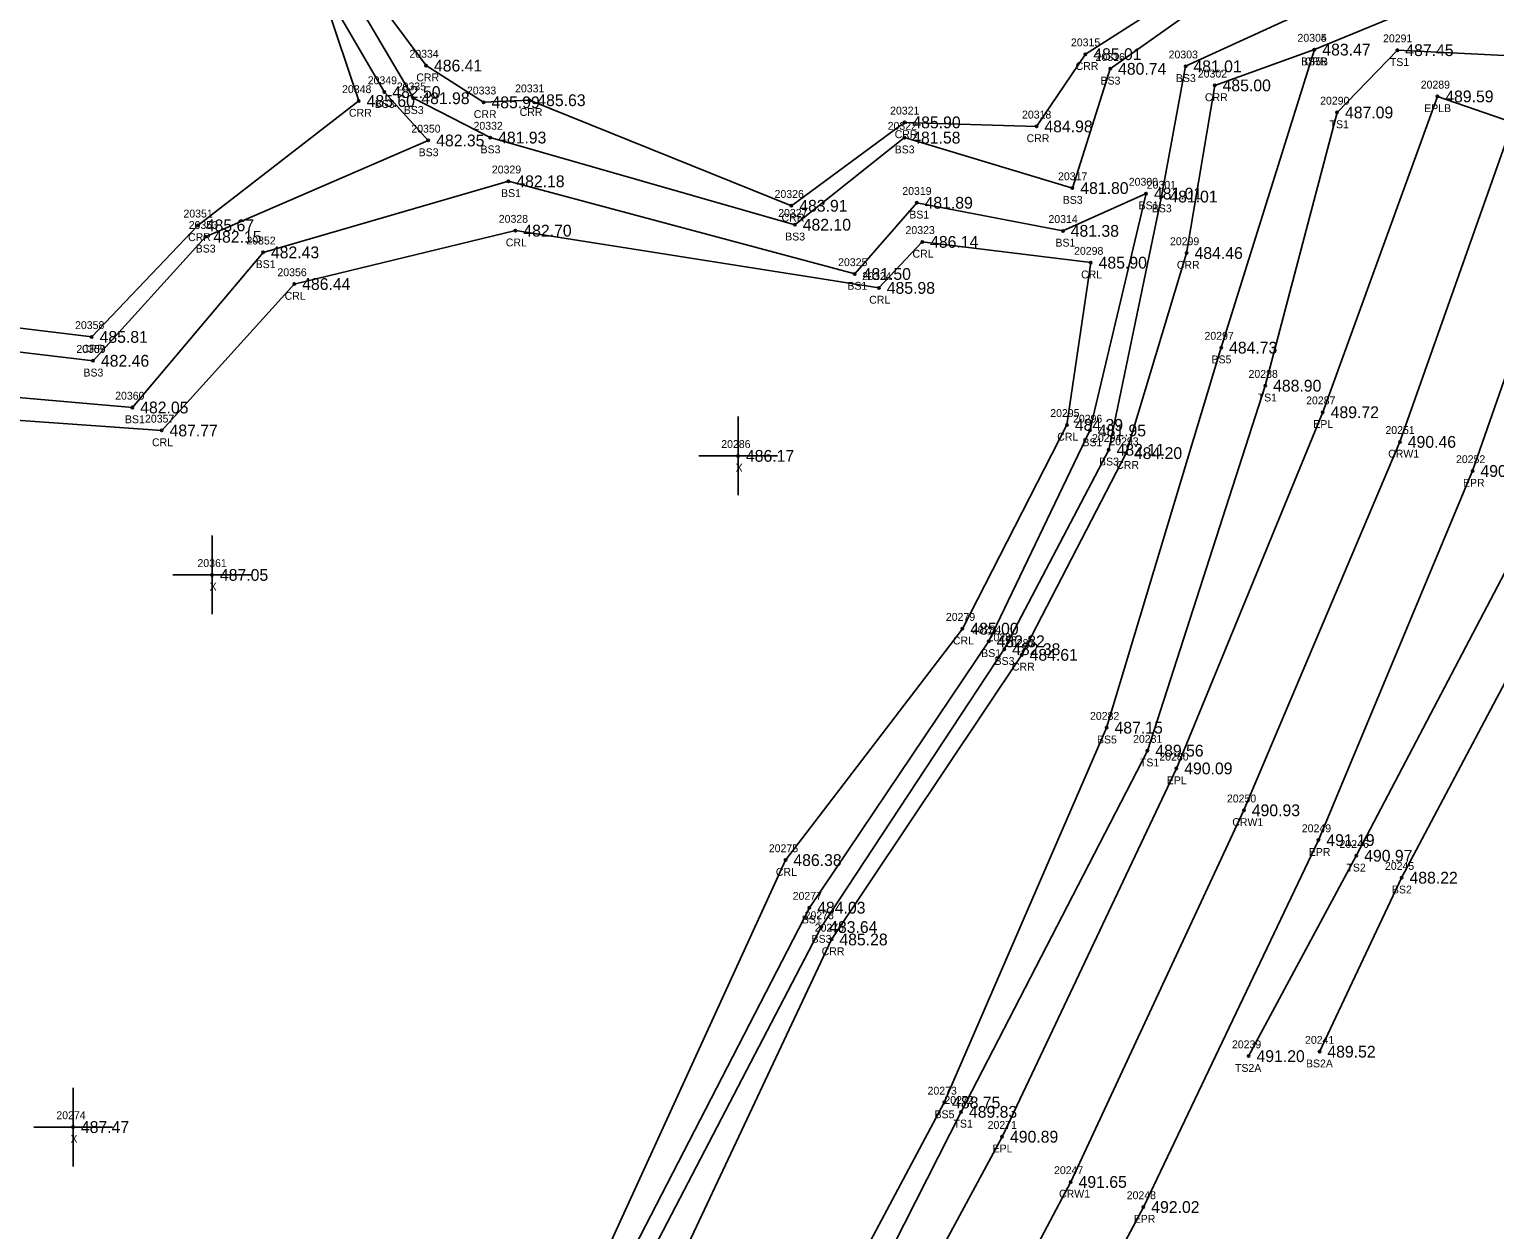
# Model space of a CAD drawing. Extents: x 1649406 to 1650436, y 896752 to 898178.
# Drawn here: x 1649688.5 to 1649874.8, y 897267.9 to 897420.5 of the extents above; entities that cross this region are included whole.
import ezdxf

# ---------------------------------------------------------------- set-up
doc = ezdxf.new("R2010")
doc.units = 0
for name, color, linetype in [('RD_DTM_BkLn1', 7, 'Continuous'), ('RD_DTM_BkLn2', 7, 'Continuous'), ('RD_DTM_BkLn_txCode', 7, 'Continuous'), ('RD_EX_H2O', 7, 'Continuous'), ('RD_EX_H2O_txCode', 7, 'Continuous'), ('RD_EX_Misc', 7, 'Continuous'), ('RD_EX_Misc_txCode', 7, 'Continuous'), ('RD_EX_Road', 7, 'Continuous'), ('RD_EX_Road_txCode', 7, 'Continuous'), ('RD_EX_TX_H2O_ELEV', 7, 'Continuous'), ('RD_EX_TX_Misc_ELEV', 7, 'Continuous'), ('RD_EX_TX_Road_ELEV', 7, 'Continuous'), ('RD_HC_Survey_ELEV', 7, 'Continuous'), ('RD_HC_Survey_txCode', 7, 'Continuous'), ('RD_SMD_Locator', 7, 'Continuous')]:
    doc.layers.add(name, color=color, linetype=linetype)

msp = doc.modelspace()

# ---------------------------------------------------------------- linework, layer by layer
at = {"layer": 'RD_DTM_BkLn1'}
msp.add_lwpolyline([(1649466.79, 896799.14), (1649494.97, 896834.25), (1649557.53, 896909.97), (1649590.88, 896950.41), (1649622.36, 896988.16), (1649622.36, 896988.48), (1649654.33, 897027.92), (1649685.38, 897067.52), (1649715.96, 897107.48), (1649743.64, 897146.32), (1649771.01, 897187.23), (1649797.64, 897230.08), (1649820.89, 897273.98), (1649842.91, 897321.22), (1649862.74, 897368.05), (1649877.08, 897408.66)], dxfattribs=at)
at = {"layer": 'RD_DTM_BkLn2'}
for points in [[(1649735.32, 897452.32), (1649735.42, 897430.71), (1649726.93, 897424.04), (1649733.64, 897412.51), (1649739.22, 897406.36), (1649710.88, 897394.12), (1649696.6, 897378.36), (1649634.62, 897385.73), (1649610.45, 897366.7), (1649591.79, 897363.75), (1649561.2, 897371.75), (1649517.81, 897366.5), (1649502.21, 897346.17), (1649434.27, 897348.24)], [(1649868.3, 897435.39), (1649845.55, 897429.41), (1649825.91, 897415.47), (1649821.11, 897400.31), (1649799.74, 897406.72), (1649785.82, 897395.65), (1649747.09, 897406.73), (1649737.33, 897411.73), (1649729.69, 897424.71), (1649738.08, 897430.82), (1649737.7, 897451.57)], [(1649604.6, 897005.75), (1649602.47, 897009.39), (1649602.3, 897017.91), (1649611.46, 897066.62), (1649609.91, 897087.35), (1649647.02, 897127.55), (1649667.48, 897155.95), (1649673.52, 897172.2), (1649701.06, 897200.6), (1649725.89, 897215.14), (1649740.6, 897244.69), (1649756.42, 897243.48), (1649789.18, 897306.38), (1649812.44, 897341.7), (1649825.72, 897367.05), (1649832.43, 897399.23), (1649835.49, 897415.79), (1649852.17, 897423.43), (1649870.24, 897429.91)], [(1649709.8, 897128.5), (1649729, 897156.36), (1649754.58, 897196.69), (1649780.91, 897239.21), (1649804.81, 897284.08), (1649825.46, 897331.72), (1649840.02, 897380.03), (1649851.88, 897417.91)], [(1649711.48, 897127.33), (1649731.83, 897154.08), (1649758, 897194.49), (1649783.81, 897237.31), (1649806.95, 897282.89), (1649830.65, 897328.8), (1649845.62, 897375.19), (1649854.76, 897409.92), (1649862.43, 897417.84), (1649895.58, 897416.19)], [(1649852.52, 897290.54), (1649862.96, 897312.65), (1649887.44, 897358.87), (1649901.31, 897404.88), (1649900.89, 897412.99), (1649895.58, 897416.19)], [(1649843.51, 897289.97), (1649857.2, 897315.44), (1649880.99, 897360.81), (1649894.26, 897406.78), (1649892.22, 897410.41)], [(1649755.02, 897245.48), (1649787.66, 897308.84), (1649810.46, 897342.7), (1649823.33, 897369.5), (1649830.47, 897399.61), (1649819.89, 897394.87), (1649801.31, 897398.44), (1649793.44, 897389.39), (1649749.41, 897401.17), (1649718.21, 897392.14), (1649701.59, 897372.42), (1649632.22, 897378.5), (1649614.16, 897360.06), (1649591.9, 897357.3), (1649588.7, 897317.57), (1649583.25, 897284.44)]]:
    msp.add_lwpolyline(points, dxfattribs=at)
at = {"layer": 'RD_EX_H2O'}
for points in [[(1649733.89, 897452.78), (1649733.23, 897431.68), (1649726.08, 897424.3), (1649730.38, 897411.38), (1649709.93, 897395.57), (1649696.43, 897381.39), (1649633.87, 897388.98), (1649608.54, 897369.49), (1649592.36, 897367.34), (1649564.26, 897376.33), (1649519.76, 897372.2), (1649499.24, 897352.4), (1649435.41, 897352.44)], [(1649868.8, 897437.77), (1649846.16, 897432.3), (1649822.76, 897417.33), (1649816.54, 897408.15), (1649799.76, 897408.66), (1649785.38, 897398.06), (1649752.08, 897411.48), (1649746.25, 897411.21), (1649738.94, 897415.88), (1649733.55, 897423.08), (1649741.13, 897430.63), (1649738.72, 897452.07)], [(1649610.78, 897003.58), (1649606.65, 897007.8), (1649603.49, 897018.01), (1649613.66, 897065.71), (1649613.8, 897087.62), (1649648.77, 897123.4), (1649673.15, 897145.36), (1649677.84, 897170.04), (1649704.36, 897195), (1649732.98, 897211.32), (1649741.05, 897244.13), (1649760.18, 897240.39), (1649790.48, 897304.8), (1649814.66, 897340.98), (1649827.92, 897366.62), (1649835.63, 897392.05), (1649839.2, 897413.36), (1649851.88, 897417.91), (1649868.27, 897424.7)], [(1649753.58, 897247.01), (1649784.63, 897314.89), (1649807.13, 897344.3), (1649820.41, 897370.21), (1649823.44, 897390.83), (1649802.01, 897393.47), (1649796.5, 897387.62), (1649750.3, 897394.9), (1649722.18, 897388.11), (1649705.32, 897369.5), (1649633.55, 897374.58), (1649615.45, 897358.48), (1649595.58, 897353.05), (1649593.32, 897314.38), (1649587.49, 897281.56)]]:
    msp.add_lwpolyline(points, dxfattribs=at)
at = {"layer": 'RD_EX_Misc'}
for p, q in [((1649778.6, 897361.27), (1649778.6, 897371.27)), ((1649773.6, 897366.27), (1649783.6, 897366.27)), ((1649711.73, 897346.14), (1649711.73, 897356.14)), ((1649706.73, 897351.14), (1649716.73, 897351.14)), ((1649694.05, 897275.96), (1649694.05, 897285.96)), ((1649689.05, 897280.96), (1649699.05, 897280.96))]:
    msp.add_line(p, q, dxfattribs=at)
at = {"layer": 'RD_EX_Road'}
for points in [[(1649459.38, 896805.71), (1649486.55, 896839.62), (1649513.65, 896873.34), (1649538.22, 896902.56), (1649549.43, 896916.62), (1649583.1, 896957.27), (1649614.8, 896995.02), (1649647.06, 897035.69), (1649677.62, 897074.51), (1649708.33, 897114.44), (1649735.5, 897151.61), (1649762.11, 897192.19), (1649788.21, 897235.29), (1649812.17, 897279.73), (1649834.32, 897326.54), (1649852.94, 897371.82), (1649867.51, 897411.96)], [(1649892.22, 897410.41), (1649886.55, 897406.09), (1649877.08, 897408.66), (1649867.51, 897411.96)], [(1649474.75, 896792.65), (1649502.78, 896827.35), (1649565.2, 896903.92), (1649598.28, 896943.71), (1649629.8, 896982.26), (1649667.92, 897029.33), (1649693.13, 897061.44), (1649723.58, 897101.84), (1649752.37, 897141.09), (1649779.72, 897182.3), (1649806.12, 897225.84), (1649830.13, 897270.79), (1649852.39, 897317.43), (1649871.98, 897364.35), (1649886.55, 897406.09)]]:
    msp.add_lwpolyline(points, dxfattribs=at)
at = {"layer": 'RD_SMD_Locator'}
for centre in [(1649822.76, 897417.33), (1649851.88, 897417.91), (1649851.88, 897417.91), (1649862.43, 897417.84), (1649738.94, 897415.88), (1649825.91, 897415.47), (1649835.49, 897415.79), (1649839.2, 897413.36), (1649730.38, 897411.38), (1649733.64, 897412.51), (1649737.33, 897411.73), (1649752.08, 897411.48), (1649867.51, 897411.96), (1649746.25, 897411.21), (1649854.76, 897409.92), (1649799.76, 897408.66), (1649816.54, 897408.15), (1649739.22, 897406.36), (1649747.09, 897406.73), (1649799.74, 897406.72), (1649749.41, 897401.17), (1649821.11, 897400.31), (1649801.31, 897398.44), (1649830.47, 897399.61), (1649832.43, 897399.23), (1649785.38, 897398.06), (1649709.93, 897395.57), (1649750.3, 897394.9), (1649785.82, 897395.65), (1649819.89, 897394.87), (1649710.88, 897394.12), (1649802.01, 897393.47), (1649718.21, 897392.14), (1649835.63, 897392.05), (1649793.44, 897389.39), (1649823.44, 897390.83), (1649722.18, 897388.11), (1649796.5, 897387.62), (1649696.43, 897381.39), (1649840.02, 897380.03), (1649696.6, 897378.36), (1649845.62, 897375.19), (1649701.59, 897372.42), (1649852.94, 897371.82), (1649705.32, 897369.5), (1649820.41, 897370.21), (1649823.33, 897369.5), (1649825.72, 897367.05), (1649862.74, 897368.05), (1649778.6, 897366.27), (1649827.92, 897366.62), (1649871.98, 897364.35), (1649711.73, 897351.14), (1649807.13, 897344.3), (1649810.46, 897342.7), (1649812.44, 897341.7), (1649814.66, 897340.98), (1649825.46, 897331.72), (1649830.65, 897328.8), (1649834.32, 897326.54), (1649842.91, 897321.22), (1649852.39, 897317.43), (1649784.63, 897314.89), (1649857.2, 897315.44), (1649862.96, 897312.65), (1649787.66, 897308.84), (1649789.18, 897306.38), (1649790.48, 897304.8), (1649852.52, 897290.54), (1649843.51, 897289.97), (1649804.81, 897284.08), (1649806.95, 897282.89), (1649694.05, 897280.96), (1649812.17, 897279.73), (1649820.89, 897273.98), (1649830.13, 897270.79)]:
    msp.add_circle(centre, 0.15, dxfattribs=at)

# ---------------------------------------------------------------- texts
at = {"layer": 'RD_DTM_BkLn_txCode'}
for s, p in [('20305', (1649849.72, 897418.91)), ('20291', (1649860.6, 897418.84)), ('20316', (1649824.05, 897416.47)), ('20303', (1649833.34, 897416.79)), ('BS5B', (1649850.18, 897415.91)), ('TS1', (1649861.47, 897415.84)), ('20349', (1649731.52, 897413.51)), ('20335', (1649735.21, 897412.73)), ('BS3', (1649824.68, 897413.47)), ('BS3', (1649834.26, 897413.79)), ('BS3', (1649732.41, 897410.51)), ('20290', (1649852.6, 897410.92)), ('BS3', (1649736.1, 897409.73)), ('20350', (1649737.06, 897407.36)), ('20332', (1649744.97, 897407.73)), ('20322', (1649797.62, 897407.72)), ('TS1', (1649853.8, 897407.92)), ('BS3', (1649737.99, 897404.36)), ('BS3', (1649745.86, 897404.73)), ('BS3', (1649798.51, 897404.72)), ('20329', (1649747.3, 897402.17)), ('20317', (1649819.28, 897401.31)), ('20319', (1649799.48, 897399.44)), ('20300', (1649828.27, 897400.61)), ('20301', (1649830.56, 897400.23)), ('BS1', (1649748.47, 897399.17)), ('BS3', (1649819.88, 897398.31)), ('BS1', (1649829.52, 897397.61)), ('20327', (1649783.7, 897396.65)), ('BS1', (1649800.37, 897396.44)), ('20314', (1649818.06, 897395.87)), ('BS3', (1649831.2, 897397.23)), ('20353', (1649708.76, 897395.12)), ('BS3', (1649709.65, 897392.12)), ('20352', (1649716.09, 897393.14)), ('BS3', (1649784.59, 897393.65)), ('BS1', (1649818.95, 897392.87)), ('BS1', (1649717.27, 897390.14)), ('20325', (1649791.32, 897390.39)), ('BS1', (1649792.5, 897387.39)), ('20297', (1649837.9, 897381.03)), ('20359', (1649694.48, 897379.36)), ('BS5', (1649838.79, 897378.03)), ('BS3', (1649695.37, 897376.36)), ('20288', (1649843.5, 897376.19)), ('20360', (1649699.41, 897373.42)), ('TS1', (1649844.66, 897373.19)), ('BS1', (1649700.65, 897370.42)), ('20296', (1649821.18, 897370.5)), ('20294', (1649823.6, 897368.05)), ('BS1', (1649822.38, 897367.5)), ('BS3', (1649824.49, 897365.05)), ('20284', (1649808.34, 897343.7)), ('20285', (1649810.32, 897342.7)), ('BS1', (1649809.51, 897340.7)), ('BS3', (1649811.21, 897339.7)), ('20282', (1649823.34, 897332.72)), ('BS5', (1649824.23, 897329.72)), ('20281', (1649828.82, 897329.8)), ('TS1', (1649829.69, 897326.8)), ('20246', (1649855.06, 897316.44)), ('20245', (1649860.84, 897313.65)), ('TS2', (1649855.95, 897313.44)), ('BS2', (1649861.73, 897310.65)), ('20277', (1649785.54, 897309.84)), ('BS1', (1649786.71, 897306.84)), ('20278', (1649787.06, 897307.38)), ('BS3', (1649787.95, 897304.38)), ('20241', (1649850.68, 897291.54)), ('20239', (1649841.39, 897290.97)), ('TS2A', (1649841.78, 897287.97)), ('BS2A', (1649850.8, 897288.54)), ('20273', (1649802.69, 897285.08)), ('20272', (1649804.83, 897283.89)), ('BS5', (1649803.58, 897282.08)), ('TS1', (1649805.99, 897280.89))]:
    msp.add_text(s, height=1, dxfattribs=at).set_placement(p)
at = {"layer": 'RD_EX_H2O_txCode'}
for s, p in [('20315', (1649820.92, 897418.33)), ('20304', (1649849.72, 897418.91)), ('20334', (1649736.82, 897416.88)), ('CRR', (1649821.51, 897415.33)), ('20302', (1649837.05, 897414.36)), ('CRR', (1649850.62, 897415.91)), ('20348', (1649728.26, 897412.38)), ('CRR', (1649737.69, 897413.88)), ('20331', (1649750.25, 897412.48)), ('20333', (1649744.13, 897412.21)), ('CRR', (1649837.95, 897411.36)), ('CRR', (1649729.13, 897409.38)), ('CRR', (1649745, 897409.21)), ('CRR', (1649750.83, 897409.48)), ('20321', (1649797.93, 897409.66)), ('20318', (1649814.7, 897409.15)), ('CRR', (1649798.51, 897406.66)), ('CRR', (1649815.28, 897406.15)), ('20326', (1649783.24, 897399.06)), ('20351', (1649708.09, 897396.57)), ('20328', (1649748.18, 897395.9)), ('CRR', (1649784.13, 897396.06)), ('20323', (1649799.89, 897394.47)), ('CRR', (1649708.68, 897393.57)), ('CRL', (1649749.07, 897392.9)), ('20299', (1649833.51, 897393.05)), ('CRL', (1649800.78, 897391.47)), ('20298', (1649821.32, 897391.83)), ('CRR', (1649834.38, 897390.05)), ('20356', (1649720.04, 897389.11)), ('20324', (1649794.38, 897388.62)), ('CRL', (1649822.21, 897388.83)), ('CRL', (1649720.95, 897386.11)), ('CRL', (1649795.27, 897385.62)), ('20358', (1649694.31, 897382.39)), ('CRR', (1649695.18, 897379.39)), ('20357', (1649703.2, 897370.5)), ('20295', (1649818.29, 897371.21)), ('CRL', (1649819.18, 897368.21)), ('CRL', (1649704.09, 897367.5)), ('20293', (1649825.8, 897367.62)), ('CRR', (1649826.67, 897364.62)), ('20279', (1649805.02, 897345.3)), ('CRL', (1649805.91, 897342.3)), ('20283', (1649812.54, 897341.98)), ('CRR', (1649813.41, 897338.98)), ('20275', (1649782.51, 897315.89)), ('CRL', (1649783.4, 897312.89)), ('20276', (1649788.34, 897305.8)), ('CRR', (1649789.23, 897302.8))]:
    msp.add_text(s, height=1, dxfattribs=at).set_placement(p)
at = {"layer": 'RD_EX_Misc_txCode'}
for s, p in [('20286', (1649776.46, 897367.27)), ('X', (1649778.29, 897364.27)), ('20361', (1649709.87, 897352.14)), ('X', (1649711.41, 897349.14)), ('20274', (1649691.93, 897281.96)), ('X', (1649693.73, 897278.96))]:
    msp.add_text(s, height=1, dxfattribs=at).set_placement(p)
at = {"layer": 'RD_EX_Road_txCode'}
for s, p in [('20289', (1649865.39, 897412.96)), ('EPLB', (1649865.83, 897409.96)), ('20287', (1649850.82, 897372.82)), ('EPL', (1649851.73, 897369.82)), ('20252', (1649869.87, 897365.35)), ('EPR', (1649870.76, 897362.35)), ('20280', (1649832.16, 897327.54)), ('EPL', (1649833.11, 897324.54)), ('20249', (1649850.27, 897318.43)), ('EPR', (1649851.16, 897315.43)), ('20271', (1649810.33, 897280.73)), ('EPL', (1649810.96, 897277.73)), ('20248', (1649828.01, 897271.79)), ('EPR', (1649828.9, 897268.79))]:
    msp.add_text(s, height=1, dxfattribs=at).set_placement(p)
at = {"layer": 'RD_EX_TX_H2O_ELEV'}
for s, p in [('485.01', (1649823.76, 897416.58)), ('483.47', (1649852.88, 897417.16)), ('486.41', (1649739.94, 897415.13)), ('485.00', (1649840.2, 897412.61)), ('485.60', (1649731.38, 897410.63)), ('485.99', (1649747.25, 897410.46)), ('485.63', (1649753.08, 897410.73)), ('485.90', (1649800.76, 897407.91)), ('484.98', (1649817.54, 897407.4)), ('483.91', (1649786.38, 897397.31)), ('485.67', (1649710.93, 897394.82)), ('482.70', (1649751.3, 897394.15)), ('486.14', (1649803.01, 897392.72)), ('485.90', (1649824.44, 897390.08)), ('484.46', (1649836.63, 897391.3)), ('486.44', (1649723.18, 897387.36)), ('485.98', (1649797.5, 897386.87)), ('485.81', (1649697.43, 897380.64)), ('484.39', (1649821.41, 897369.46)), ('487.77', (1649706.32, 897368.75)), ('484.20', (1649828.92, 897365.87)), ('485.00', (1649808.13, 897343.55)), ('484.61', (1649815.66, 897340.23)), ('486.38', (1649785.63, 897314.14)), ('485.28', (1649791.48, 897304.05))]:
    msp.add_text(s, height=1.5, dxfattribs=at).set_placement(p)
at = {"layer": 'RD_EX_TX_Misc_ELEV'}
for s, p in [('483.47', (1649852.88, 897417.16)), ('487.45', (1649863.43, 897417.09)), ('480.74', (1649826.91, 897414.72)), ('481.01', (1649836.49, 897415.04)), ('482.50', (1649734.64, 897411.76)), ('481.98', (1649738.33, 897410.98)), ('487.09', (1649855.76, 897409.17)), ('482.35', (1649740.22, 897405.61)), ('481.93', (1649748.09, 897405.98)), ('481.58', (1649800.74, 897405.97)), ('482.18', (1649750.41, 897400.42)), ('481.80', (1649822.11, 897399.56)), ('481.01', (1649831.47, 897398.86)), ('481.89', (1649802.31, 897397.69)), ('481.01', (1649833.43, 897398.48)), ('482.15', (1649711.88, 897393.37)), ('482.10', (1649786.82, 897394.9)), ('481.38', (1649820.89, 897394.12)), ('482.43', (1649719.21, 897391.39)), ('481.50', (1649794.44, 897388.64)), ('484.73', (1649841.02, 897379.28)), ('482.46', (1649697.6, 897377.61)), ('488.90', (1649846.62, 897374.44)), ('482.05', (1649702.59, 897371.67)), ('481.95', (1649824.33, 897368.75)), ('486.17', (1649779.6, 897365.52)), ('482.11', (1649826.72, 897366.3)), ('487.05', (1649712.73, 897350.39)), ('482.82', (1649811.46, 897341.95)), ('482.38', (1649813.44, 897340.95)), ('487.15', (1649826.46, 897330.97)), ('489.56', (1649831.65, 897328.05)), ('490.97', (1649858.2, 897314.69)), ('488.22', (1649863.96, 897311.9)), ('484.03', (1649788.66, 897308.09)), ('483.64', (1649790.18, 897305.63)), ('491.20', (1649844.51, 897289.22)), ('489.52', (1649853.52, 897289.79)), ('488.75', (1649805.81, 897283.33)), ('489.83', (1649807.95, 897282.14)), ('487.47', (1649695.05, 897280.21))]:
    msp.add_text(s, height=1.5, dxfattribs=at).set_placement(p)
at = {"layer": 'RD_EX_TX_Road_ELEV'}
for s, p in [('489.59', (1649868.51, 897411.21)), ('489.72', (1649853.94, 897371.07)), ('490.95', (1649872.98, 897363.6)), ('490.09', (1649835.32, 897325.79)), ('491.19', (1649853.39, 897316.68)), ('490.89', (1649813.17, 897278.98)), ('492.02', (1649831.13, 897270.04))]:
    msp.add_text(s, height=1.5, dxfattribs=at).set_placement(p)
at = {"layer": 'RD_HC_Survey_ELEV'}
for s, p in [('490.46', (1649863.74, 897367.3)), ('490.93', (1649843.91, 897320.47)), ('491.65', (1649821.89, 897273.23))]:
    msp.add_text(s, height=1.5, dxfattribs=at).set_placement(p)
at = {"layer": 'RD_HC_Survey_txCode'}
for s, p in [('20251', (1649860.9, 897369.05)), ('CRW1', (1649861.25, 897366.05)), ('20250', (1649840.75, 897322.22)), ('CRW1', (1649841.43, 897319.22)), ('20247', (1649818.77, 897274.98)), ('CRW1', (1649819.41, 897271.98))]:
    msp.add_text(s, height=1, dxfattribs=at).set_placement(p)

doc.saveas('drawing.dxf')
